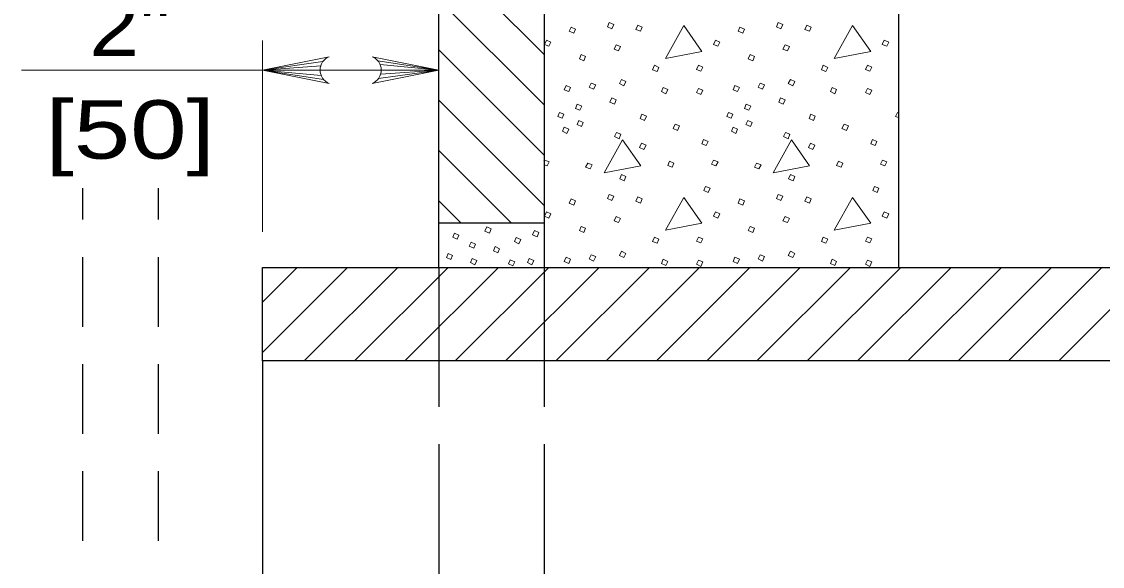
# Model space of a CAD drawing. Extents: x 1083.1 to 1117.1, y 719.4 to 741.4.
# Drawn here: x 1102.136 to 1105.022, y 727.592 to 729.047 of the extents above; entities that cross this region are included whole.
import ezdxf
from ezdxf.enums import TextEntityAlignment as Align

# ---------------------------------------------------------------- set-up
doc = ezdxf.new("R2010")
doc.units = 0
doc.header["$LTSCALE"] = 0.062
doc.linetypes.add('LONG_DASHED', pattern=[7.5, 6, -1.5])
doc.linetypes.add('MEDIUM_DASHED', pattern=[4.5, 3, -1.5])
doc.layers.add('1', color=7, linetype='Continuous', lineweight=13)

msp = doc.modelspace()

# ---------------------------------------------------------------- linework, layer by layer
at = {"layer": '1', "lineweight": 25}
for p, q in [((1104.47725, 731.29617), (1104.47725, 728.39042)), ((1103.53142, 729.51175), (1103.53142, 728.39042)), ((1103.53142, 728.67467), (1103.53275, 728.67733)), ((1103.53142, 728.50908), (1103.25025, 728.50908)), ((1102.779, 728.14075), (1102.779, 726.743))]:
    msp.add_line(p, q, dxfattribs=at)
at = {"layer": '1'}
for p, q in [((1103.25025, 729.24008), (1103.53142, 728.959)), ((1103.25025, 729.10583), (1103.53142, 728.82475)), ((1102.779, 728.48542), (1102.779, 728.997)), ((1103.25025, 728.97158), (1103.53142, 728.6905)), ((1102.94025, 728.94042), (1102.779, 728.91783)), ((1102.93475, 728.92925), (1102.779, 728.91783)), ((1103.08717, 728.94275), (1103.25025, 728.91783)), ((1103.09333, 728.93233), (1103.25025, 728.91783)), ((1102.13592, 728.91783), (1103.25025, 728.91783)), ((1102.93308, 728.91783), (1102.779, 728.91783)), ((1102.93592, 728.90333), (1102.779, 728.91783)), ((1102.94208, 728.89292), (1102.779, 728.91783)), ((1103.08908, 728.89533), (1103.25025, 728.91783)), ((1103.0945, 728.9065), (1103.25025, 728.91783)), ((1103.09617, 728.91783), (1103.25025, 728.91783)), ((1103.25025, 728.83725), (1103.53142, 728.55608)), ((1104.47442, 728.80475), (1104.47725, 728.80358)), ((1103.25025, 728.703), (1103.44408, 728.50908)), ((1104.90517, 728.14075), (1105.47208, 728.70758)), ((1103.25025, 728.56867), (1103.30983, 728.50908)), ((1102.779, 728.2975), (1102.872, 728.39042)), ((1102.779, 728.16317), (1103.00625, 728.39042)), ((1102.89083, 728.14075), (1103.14058, 728.39042)), ((1103.02508, 728.14075), (1103.27483, 728.39042)), ((1103.15942, 728.14075), (1103.40917, 728.39042)), ((1103.29375, 728.14075), (1103.5435, 728.39042)), ((1103.42808, 728.14075), (1103.67775, 728.39042)), ((1103.56233, 728.14075), (1103.81208, 728.39042)), ((1103.69658, 728.14075), (1103.94633, 728.39042)), ((1103.83092, 728.14075), (1104.08067, 728.39042)), ((1103.96517, 728.14075), (1104.21492, 728.39042)), ((1104.0995, 728.14075), (1104.34917, 728.39042)), ((1104.23375, 728.14075), (1104.4835, 728.39042)), ((1104.368, 728.14075), (1104.61775, 728.39042)), ((1104.50233, 728.14075), (1104.75208, 728.39042)), ((1104.63658, 728.14075), (1104.88633, 728.39042)), ((1104.77092, 728.14075), (1105.02058, 728.39042))]:
    msp.add_line(p, q, dxfattribs=at)
at = {"layer": '1', "linetype": 'MEDIUM_DASHED', "lineweight": 25}
for p, q in [((1102.29925, 727.08817), (1102.29925, 728.60258)), ((1102.50175, 727.08817), (1102.50175, 728.60258))]:
    msp.add_line(p, q, dxfattribs=at)
at = {"layer": '1', "linetype": 'LONG_DASHED', "lineweight": 25}
for p, q in [((1103.25025, 728.39042), (1103.25025, 726.48767)), ((1103.53142, 728.39042), (1103.53142, 726.48767))]:
    msp.add_line(p, q, dxfattribs=at)
at = {"layer": '1', "lineweight": 25}
for points in [[(1103.25025, 728.39042), (1103.25025, 730.21208), (1103.59067, 730.21208), (1103.68792, 730.7725)], [(1105.59133, 728.72533), (1106.07083, 728.74583), (1106.07083, 728.52117), (1105.59625, 728.47875), (1105.59625, 728.39042), (1105.59625, 728.14075), (1102.779, 728.14075), (1102.779, 728.39042)], [(1102.779, 728.39042), (1103.53142, 728.39042), (1104.47725, 728.39042), (1105.09267, 728.39042)]]:
    msp.add_lwpolyline(points, dxfattribs=at)
at = {"layer": '1'}
for points in [[(1103.70525, 729.04442), (1103.71708, 729.03967), (1103.71233, 729.02783), (1103.7005, 729.03333)], [(1104.15625, 729.04442), (1104.16817, 729.03967), (1104.16342, 729.02783), (1104.1515, 729.03333)], [(1103.60317, 729.03258), (1103.615, 729.02708), (1103.61025, 729.016), (1103.59842, 729.0215)], [(1103.78125, 729.03808), (1103.79308, 729.03258), (1103.78833, 729.0215), (1103.77642, 729.02625)], [(1103.90383, 729.0365), (1103.85483, 728.94875), (1103.95208, 728.96767)], [(1104.05417, 729.03258), (1104.06608, 729.02708), (1104.06133, 729.016), (1104.04942, 729.0215)], [(1104.23225, 729.03808), (1104.24408, 729.03258), (1104.23933, 729.0215), (1104.2275, 729.02625)], [(1104.35492, 729.0365), (1104.30583, 728.94875), (1104.40317, 728.96767)], [(1103.5375, 728.99775), (1103.54933, 728.99225), (1103.54383, 728.98117), (1103.53192, 728.98592)], [(1103.72342, 728.98508), (1103.73533, 728.98033), (1103.72975, 728.96925), (1103.71792, 728.974)], [(1103.9885, 728.99775), (1104.00042, 728.99225), (1103.99483, 728.98117), (1103.983, 728.98592)], [(1104.1745, 728.98508), (1104.18633, 728.98033), (1104.18083, 728.96925), (1104.16892, 728.974)], [(1104.43958, 728.99775), (1104.45142, 728.99225), (1104.44592, 728.98117), (1104.434, 728.98592)], [(1103.63008, 728.959), (1103.64192, 728.95425), (1103.63717, 728.94242), (1103.62533, 728.94792)], [(1104.08108, 728.959), (1104.093, 728.95425), (1104.08825, 728.94242), (1104.07633, 728.94792)], [(1103.8255, 728.9305), (1103.83742, 728.925), (1103.83267, 728.91392), (1103.82075, 728.91867)], [(1103.94342, 728.9305), (1103.95525, 728.92575), (1103.94975, 728.91467), (1103.93792, 728.91942)], [(1104.27658, 728.9305), (1104.28842, 728.925), (1104.28367, 728.91392), (1104.27183, 728.91867)], [(1104.3945, 728.9305), (1104.40633, 728.92575), (1104.40075, 728.91467), (1104.38892, 728.91942)], [(1103.58975, 728.87675), (1103.60158, 728.87117), (1103.59683, 728.86008), (1103.585, 728.86483)], [(1103.657, 728.88308), (1103.66883, 728.87825), (1103.66333, 728.86642), (1103.65142, 728.872)], [(1103.73767, 728.8925), (1103.74958, 728.887), (1103.744, 728.87592), (1103.73217, 728.88142)], [(1103.84925, 728.87117), (1103.86117, 728.86567), (1103.85642, 728.85458), (1103.8445, 728.86008)], [(1103.94342, 728.86883), (1103.95525, 728.86408), (1103.94975, 728.85217), (1103.93792, 728.85775)], [(1104.04075, 728.87675), (1104.05258, 728.87117), (1104.04783, 728.86008), (1104.036, 728.86483)], [(1104.108, 728.88308), (1104.11992, 728.87825), (1104.11433, 728.86642), (1104.1025, 728.872)], [(1104.18875, 728.8925), (1104.20058, 728.887), (1104.19508, 728.87592), (1104.18317, 728.88142)], [(1104.30033, 728.87117), (1104.31217, 728.86567), (1104.30742, 728.85458), (1104.29558, 728.86008)], [(1104.3945, 728.86883), (1104.40633, 728.86408), (1104.40075, 728.85217), (1104.38892, 728.85775)], [(1103.71158, 728.8435), (1103.72342, 728.83792), (1103.71867, 728.82683), (1103.70683, 728.83242)], [(1104.16258, 728.8435), (1104.1745, 728.83792), (1104.16975, 728.82683), (1104.15783, 728.83242)], [(1103.61975, 728.82683), (1103.63167, 728.82133), (1103.62692, 728.81025), (1103.615, 728.815)], [(1104.07083, 728.82683), (1104.08267, 728.82133), (1104.07792, 728.81025), (1104.06608, 728.815)], [(1103.57233, 728.80475), (1103.58417, 728.8), (1103.57942, 728.78892), (1103.56758, 728.79367)], [(1103.62375, 728.78333), (1103.63558, 728.77783), (1103.63083, 728.76675), (1103.619, 728.77225)], [(1103.79225, 728.8), (1103.80417, 728.79442), (1103.79942, 728.78333), (1103.7875, 728.78808)], [(1104.02333, 728.80475), (1104.03525, 728.8), (1104.0305, 728.78892), (1104.01858, 728.79367)], [(1104.07475, 728.78333), (1104.08667, 728.77783), (1104.08192, 728.76675), (1104.07, 728.77225)], [(1104.24333, 728.8), (1104.25517, 728.79442), (1104.25042, 728.78333), (1104.23858, 728.78808)], [(1103.585, 728.76517), (1103.59683, 728.75958), (1103.59208, 728.7485), (1103.58025, 728.75408)], [(1103.72425, 728.75092), (1103.73608, 728.74617), (1103.73133, 728.73433), (1103.7195, 728.73983)], [(1103.88092, 728.77308), (1103.89275, 728.76833), (1103.88725, 728.75642), (1103.87533, 728.762)], [(1104.036, 728.76517), (1104.04783, 728.75958), (1104.04317, 728.7485), (1104.03125, 728.75408)], [(1104.17525, 728.75092), (1104.18717, 728.74617), (1104.18242, 728.73433), (1104.1705, 728.73983)], [(1104.33192, 728.77308), (1104.34383, 728.76833), (1104.33825, 728.75642), (1104.32642, 728.762)], [(1103.74083, 728.73117), (1103.69175, 728.64333), (1103.78908, 728.66233)], [(1103.7915, 728.72242), (1103.80333, 728.71692), (1103.79783, 728.70583), (1103.78592, 728.71058)], [(1103.95683, 728.73192), (1103.96875, 728.72717), (1103.964, 728.71608), (1103.95208, 728.72083)], [(1104.19192, 728.73117), (1104.14283, 728.64333), (1104.24017, 728.66233)], [(1104.2425, 728.72242), (1104.25442, 728.71692), (1104.24883, 728.70583), (1104.237, 728.71058)], [(1104.40792, 728.73192), (1104.41975, 728.72717), (1104.415, 728.71608), (1104.40317, 728.72083)], [(1103.6475, 728.66942), (1103.65933, 728.66467), (1103.65383, 728.65358), (1103.64192, 728.65833)], [(1103.86583, 728.67417), (1103.87775, 728.66942), (1103.873, 728.65833), (1103.86117, 728.66308)], [(1103.98375, 728.67733), (1103.99567, 728.67258), (1103.99008, 728.6615), (1103.97825, 728.66625)], [(1104.0985, 728.66942), (1104.11042, 728.66467), (1104.10483, 728.65358), (1104.093, 728.65833)], [(1104.31692, 728.67417), (1104.32875, 728.66942), (1104.324, 728.65833), (1104.31217, 728.66308)], [(1104.43483, 728.67733), (1104.44667, 728.67258), (1104.44117, 728.6615), (1104.42925, 728.66625)], [(1103.73767, 728.63858), (1103.74958, 728.63383), (1103.74483, 728.62192), (1103.73292, 728.6275)], [(1104.18875, 728.63858), (1104.20058, 728.63383), (1104.19583, 728.62192), (1104.184, 728.6275)], [(1103.96242, 728.60692), (1103.97425, 728.60217), (1103.9695, 728.59108), (1103.95767, 728.59583)], [(1104.41342, 728.60692), (1104.42533, 728.60217), (1104.42058, 728.59108), (1104.40867, 728.59583)], [(1103.70525, 728.58558), (1103.71708, 728.58083), (1103.71233, 728.56892), (1103.7005, 728.5745)], [(1103.78125, 728.57925), (1103.79308, 728.57367), (1103.78833, 728.56258), (1103.77642, 728.56733)], [(1103.90383, 728.57767), (1103.85483, 728.48983), (1103.95208, 728.50883)], [(1104.15625, 728.58558), (1104.16817, 728.58083), (1104.16342, 728.56892), (1104.1515, 728.5745)], [(1104.23225, 728.57925), (1104.24408, 728.57367), (1104.23933, 728.56258), (1104.2275, 728.56733)], [(1104.35492, 728.57767), (1104.30583, 728.48983), (1104.40317, 728.50883)], [(1103.60317, 728.57367), (1103.615, 728.56817), (1103.61025, 728.55708), (1103.59842, 728.56258)], [(1104.05417, 728.57367), (1104.06608, 728.56817), (1104.06133, 728.55708), (1104.04942, 728.56258)], [(1103.5375, 728.53883), (1103.54933, 728.53333), (1103.54383, 728.52225), (1103.53192, 728.527)], [(1103.72342, 728.52617), (1103.73533, 728.52142), (1103.72975, 728.51042), (1103.71792, 728.51517)], [(1103.9885, 728.53883), (1104.00042, 728.53333), (1103.99483, 728.52225), (1103.983, 728.527)], [(1104.1745, 728.52617), (1104.18633, 728.52142), (1104.18083, 728.51042), (1104.16892, 728.51517)], [(1104.43958, 728.53883), (1104.45142, 728.53333), (1104.44592, 728.52225), (1104.434, 728.527)], [(1103.37783, 728.49875), (1103.38967, 728.49325), (1103.38492, 728.48217), (1103.37308, 728.48767)], [(1103.63008, 728.50008), (1103.64192, 728.49533), (1103.63717, 728.4835), (1103.62533, 728.489)], [(1104.08108, 728.50008), (1104.093, 728.49533), (1104.08825, 728.4835), (1104.07633, 728.489)], [(1103.29183, 728.48225), (1103.30375, 728.47667), (1103.299, 728.46558), (1103.28708, 728.47117)], [(1103.45675, 728.47042), (1103.46867, 728.46492), (1103.46392, 728.45383), (1103.452, 728.45933)], [(1103.50508, 728.48892), (1103.51692, 728.48342), (1103.51217, 728.47233), (1103.50033, 728.47783)], [(1103.8255, 728.47158), (1103.83742, 728.46608), (1103.83267, 728.455), (1103.82075, 728.45975)], [(1103.94342, 728.47158), (1103.95525, 728.46683), (1103.94975, 728.45575), (1103.93792, 728.4605)], [(1104.27658, 728.47158), (1104.28842, 728.46608), (1104.28367, 728.455), (1104.27183, 728.45975)], [(1104.3945, 728.47158), (1104.40633, 728.46683), (1104.40075, 728.45575), (1104.38892, 728.4605)], [(1103.33608, 728.45825), (1103.348, 728.45267), (1103.34325, 728.44158), (1103.33133, 728.44717)], [(1103.40033, 728.44617), (1103.41225, 728.44058), (1103.4075, 728.4295), (1103.39558, 728.43508)], [(1103.73767, 728.43367), (1103.74958, 728.42808), (1103.744, 728.417), (1103.73217, 728.42258)], [(1104.18875, 728.43367), (1104.20058, 728.42808), (1104.19508, 728.417), (1104.18317, 728.42258)], [(1103.27492, 728.428), (1103.28683, 728.4225), (1103.28208, 728.41142), (1103.27017, 728.41692)], [(1103.33917, 728.4145), (1103.35108, 728.40892), (1103.34633, 728.39783), (1103.33442, 728.40342)], [(1103.44075, 728.41108), (1103.45258, 728.40558), (1103.44783, 728.3945), (1103.436, 728.4)], [(1103.4915, 728.4145), (1103.50342, 728.40892), (1103.49867, 728.39783), (1103.48675, 728.40342)], [(1103.58975, 728.41783), (1103.60158, 728.41225), (1103.59683, 728.40117), (1103.585, 728.40592)], [(1103.657, 728.42417), (1103.66883, 728.41942), (1103.66333, 728.4075), (1103.65142, 728.41308)], [(1103.84925, 728.41225), (1103.86117, 728.40675), (1103.85642, 728.39567), (1103.8445, 728.40117)], [(1103.94342, 728.40992), (1103.95525, 728.40517), (1103.94975, 728.39325), (1103.93792, 728.39883)], [(1104.04075, 728.41783), (1104.05258, 728.41225), (1104.04783, 728.40117), (1104.036, 728.40592)], [(1104.108, 728.42417), (1104.11992, 728.41942), (1104.11433, 728.4075), (1104.1025, 728.41308)], [(1104.30033, 728.41225), (1104.31217, 728.40675), (1104.30742, 728.39567), (1104.29558, 728.40117)], [(1104.3945, 728.40992), (1104.40633, 728.40517), (1104.40075, 728.39325), (1104.38892, 728.39883)]]:
    msp.add_lwpolyline(points, close=True, dxfattribs=at)
for points in [[(1102.95708, 728.88225), (1102.779, 728.91783), (1102.95708, 728.9535)], [(1103.07217, 728.9535), (1103.25025, 728.91783), (1103.07217, 728.88225)], [(1104.47725, 728.79067), (1104.46967, 728.79367), (1104.47442, 728.80475)], [(1103.53275, 728.67733), (1103.54458, 728.67258), (1103.53908, 728.6615), (1103.53142, 728.66458)]]:
    msp.add_lwpolyline(points, dxfattribs=at)
for centre, major_axis in [((1102.97152, 728.91786), (-0.03843, 0)), ((1103.05775, 728.91785), (0.03843, 0))]:
    msp.add_ellipse(centre, major_axis=major_axis, ratio=0.999895, start_param=5.0978942, end_param=7.4685073, dxfattribs=at)

# ---------------------------------------------------------------- texts
for s, width, p in [('2"', 1.15, (1102.42579, 728.955)), ('[50]', 1.3, (1102.42579, 728.681))]:
    msp.add_text(s, height=0.156, dxfattribs=dict(at, width=width)).set_placement(p, align=Align.CENTER)

doc.saveas('drawing.dxf')
